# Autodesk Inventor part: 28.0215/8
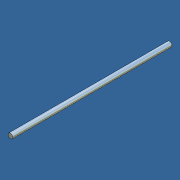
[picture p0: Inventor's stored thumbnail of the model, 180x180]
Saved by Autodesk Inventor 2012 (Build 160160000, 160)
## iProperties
Created: 2011-05
Part Number: 28.0215/8
Material: Steel
Document SubType Name: Modeling
Designer: Administrator
Density: 7.85 g/cm^3
Mass: 350.282 g
Surface Area: 151.002 cm^2
Volume: 44.6219 cm^3
Description: L = TRAVEL + 3.533"
Stock Number: 17.1741 SHAFT 12
Vendor: F
Author: Administrator
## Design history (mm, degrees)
sketch "Sketch1"
  geometry: C1 r 6 at (0, 0)
  constraints: 1 centre point
  dimensions: "d1" = 11.99998 diameter of C1
extrude "Extrusion1" new body sketch "Sketch1" stored distance "d4" = 394.546 (computed from TRAVEL); taper "d5" = 0 deg
body "Solid1"
other parameters: "TRAVEL" = 304.8 [user parameter; used in 1 equation term]
